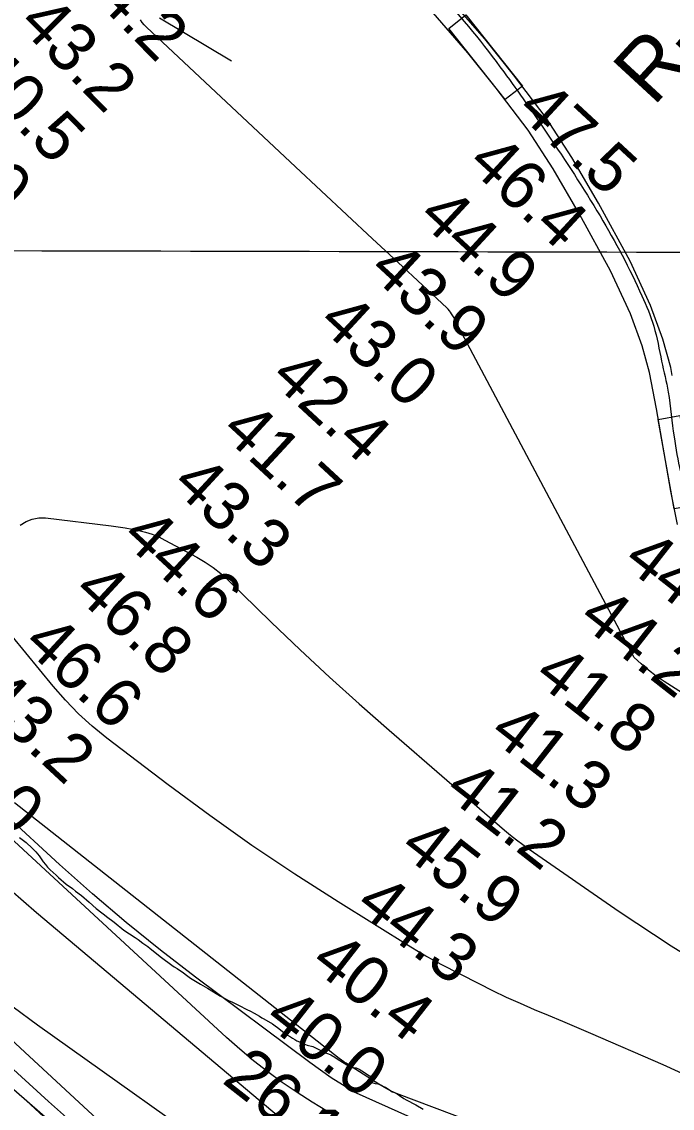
# Model space of a CAD drawing. Extents: x 3187622 to 3225504, y 800805 to 826213.
# Drawn here: x 3201041 to 3201935, y 817171 to 818665 of the extents above; entities that cross this region are included whole.
import ezdxf

# ---------------------------------------------------------------- set-up
doc = ezdxf.new("R2010")
doc.units = 0
for name, color, linetype in [('V-GRID-MAJR', 7, 'Continuous'), ('V-RIVR-EDGE', 7, 'Continuous'), ('V-RIVR-RANG', 7, 'Continuous'), ('V-RIVR-RANG-IDEN', 7, 'Continuous'), ('V-ROAD-CNTR', 7, 'Continuous'), ('V-SITE-VEGE', 7, 'Continuous'), ('V-TOPO-DPTH', 7, 'Continuous'), ('V-TOPO-MAJR', 7, 'Continuous'), ('V-TOPO-MINR', 7, 'Continuous'), ('V-TOPO-WATR', 7, 'Continuous')]:
    doc.layers.add(name, color=color, linetype=linetype)

msp = doc.modelspace()

# ---------------------------------------------------------------- linework, layer by layer
at = {"layer": 'V-GRID-MAJR'}
msp.add_spline([(3191823.839, 818371.837), (3197059.682, 818359.272), (3202295.526, 818347.468), (3207531.372, 818336.426), (3212767.22, 818326.145), (3218003.0700000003, 818316.626), (3223238.92, 818307.868), (3223238.921, 818307.868)], degree=3, dxfattribs=at)
at = {"layer": 'V-RIVR-EDGE'}
msp.add_lwpolyline([(3201136.1406451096, 817098.8818968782), (3201047.2350998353, 817181.2561007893), (3200994.754246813, 817227.8965436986)], dxfattribs=at)
at = {"layer": 'V-ROAD-CNTR'}
for points in [[(3201935.461570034, 818178.7369305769), (3201933.461920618, 818189.3653369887), (3201922.573450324, 818228.3969656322), (3201905.605787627, 818274.9007402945), (3201877.5326565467, 818335.8999269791), (3201834.216508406, 818415.3624383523), (3201797.2907217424, 818478.3515299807), (3201761.901233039, 818533.0936946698), (3201717.024386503, 818592.0773767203), (3201677.586710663, 818641.6715770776), (3201628.606678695, 818697.8135974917)], [(3201942.7374564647, 817973.6426642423), (3201933.6286105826, 818019.5790433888), (3201913.571811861, 818132.8323130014), (3201904.218079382, 818182.5486630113), (3201893.990549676, 818219.2110343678), (3201877.8422123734, 818263.4692597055), (3201850.7053434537, 818322.4340730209), (3201808.099491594, 818400.5935616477), (3201771.7412782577, 818462.6144700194), (3201737.330766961, 818515.8423053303), (3201693.3436134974, 818573.6566232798), (3201654.531289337, 818622.4644229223), (3201606.6453213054, 818677.3524025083)]]:
    msp.add_lwpolyline(points, dxfattribs=at)
for points in [[(3201705.8309982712, 818557.9533180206), (3201628.030361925, 818655.7902281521), (3201651.511220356, 818674.4623808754), (3201729.311856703, 818576.6254707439)], [(3201937.9826044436, 817994.9936622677), (3201916.184684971, 818118.0783920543), (3201945.72502012, 818123.3098927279), (3201967.5229395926, 818000.2251629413)]]:
    msp.add_lwpolyline(points, close=True, dxfattribs=at)
msp.add_spline([(3201024.1469147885, 823274.715423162), (3201018.0129270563, 823194.189584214), (3201004.718953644, 822963.7310451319), (3200987.4149882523, 822858.6972551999), (3200966.948029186, 822788.416395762), (3200937.8420873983, 822670.750631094), (3200879.4052042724, 822446.800078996), (3200861.238240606, 822331.312309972), (3200852.3482583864, 822205.904560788), (3200845.9832711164, 822103.0497664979), (3200850.494262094, 822002.651967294), (3200859.8182434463, 821900.4111717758), (3200873.148216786, 821709.08955442), (3200906.150150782, 821470.9180307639), (3200956.550049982, 821171.314629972), (3200981.83099942, 821020.504931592), (3201004.428954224, 820882.865206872), (3201024.90091328, 820767.6074373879), (3201030.704901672, 820687.434597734), (3201025.0879129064, 820574.7828230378), (3201019.728923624, 820485.638001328), (3201009.904943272, 820413.658145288), (3200981.8429993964, 820299.159374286), (3200938.6350858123, 820153.0996664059), (3200919.6651237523, 820054.1388643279), (3200905.8851513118, 819899.779173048), (3200911.078140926, 819808.036356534), (3200923.595115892, 819715.0165425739), (3200943.704075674, 819632.5057075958), (3200989.973983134, 819544.474883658), (3201077.634807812, 819388.707195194), (3201164.584633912, 819241.2794900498), (3201215.4495321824, 819169.23463414), (3201320.5073220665, 819031.1739102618), (3201438.252086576, 818874.583223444), (3201472.894017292, 818830.2363121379), (3201517.7899275, 818788.499395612), (3201613.6647357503, 818704.054564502), (3201703.731555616, 818596.021780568), (3201763.792435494, 818510.519951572), (3201836.136290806, 818397.89617682), (3201893.7711755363, 818288.104396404), (3201909.952143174, 818246.3284799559), (3201920.8531213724, 818198.082576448), (3201929.8091034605, 818155.84666092), (3201937.905087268, 818094.070784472), (3201957.718047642, 817998.595975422), (3201977.8520073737, 817926.3501199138), (3202055.382852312, 817776.5004196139), (3202147.001669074, 817623.97272467), (3202184.387594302, 817575.26282209), (3202228.252506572, 817509.5509535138), (3202265.871431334, 817464.9970426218), (3202335.4492921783, 817389.266194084), (3202595.371772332, 817156.054660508), (3202698.6155658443, 817066.2408401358), (3202845.2082726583, 816933.75410511), (3202967.1920286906, 816832.346307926), (3203084.1367948, 816744.1614842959), (3203205.803551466, 816662.3206479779), (3203334.4592941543, 816585.86980088), (3203420.0661229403, 816528.708915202), (3203529.074904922, 816448.4050758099), (3203624.28071451, 816386.379199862), (3203720.2955224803, 816332.45030772), (3203800.7433615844, 816304.608363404), (3203929.0741049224, 816241.273490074), (3204015.146932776, 816192.42558777), (3204112.488738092, 816105.381761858), (3204200.50956205, 816023.2659260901)], degree=3, dxfattribs=at)
at = {"layer": 'V-SITE-VEGE'}
for points in [[(3201037.809, 817543.368), (3201046.934, 817536.366), (3201055.403, 817528.7270000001), (3201060.1750000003, 817523.431), (3201064.617, 817517.821), (3201070.47, 817509.582), (3201073.325, 817505.953), (3201076.348, 817502.482), (3201080.174, 817498.6680000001), (3201087.997, 817491.367), (3201091.186, 817488.2170000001), (3201101.739, 817479.237), (3201110.879, 817472.888), (3201114.879, 817469.558), (3201123.2060000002, 817463.221), (3201133.764, 817454.405), (3201143.184, 817445.77), (3201150.866, 817439.61), (3201154.551, 817436.7760000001), (3201157.596, 817434.605), (3201167.842, 817426.603), (3201181.1210000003, 817415.786), (3201196.8540000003, 817405.732), (3201200.86, 817402.728), (3201207.432, 817398.05), (3201210.322, 817396.207), (3201214.168, 817393.37), (3201217.686, 817390.376), (3201232.887, 817378.055), (3201247.477, 817367.699), (3201250.686, 817365.524), (3201254.54, 817363.175)], [(3201254.54, 817363.175), (3201263.199, 817357.156), (3201267.523, 817353.821), (3201273.134, 817349.813), (3201286.622, 817341.427), (3201296.27, 817336.041), (3201310.563, 817327.15), (3201313.4590000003, 817325.631), (3201316.83, 817323.454), (3201320.846, 817321.101), (3201325.196, 817319.067), (3201329.71, 817317.191), (3201332.444, 817315.677), (3201343.552, 817310.263), (3201346.93, 817308.409), (3201350.473, 817306.715), (3201355.468, 817304.506), (3201360.455, 817301.808), (3201368.006, 817297.274), (3201371.053, 817295.265), (3201373.951, 817293.747), (3201385.682, 817286.858), (3201389.37, 817284.349), (3201392.575, 817282.012), (3201398.973, 817276.688), (3201406.186, 817271.51), (3201410.362, 817268.991), (3201413.42, 817267.308), (3201416.308, 817265.465), (3201419.363, 817263.779), (3201422.9080000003, 817262.2490000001), (3201425.647, 817260.895), (3201428.87, 817259.534), (3201433.3880000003, 817257.821), (3201441.308, 817255.552), (3201453.86, 817249.138), (3201458.372, 817247.1), (3201462.572, 817245.882), (3201465.798, 817244.518), (3201471.258, 817241.1630000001), (3201475.907, 817237.823), (3201490.042, 817229.26), (3201493.251, 817227.085), (3201497.14, 817226.524), (3201500.548, 817226.295), (3201504.904, 817224.586), (3201508.6010000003, 817222.4010000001), (3201519.193, 817215.536), (3201521.096, 817213.058), (3201520.539, 817209.495), (3201522.1010000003, 817206.214), (3201527.109, 817204.655), (3201530.355, 817204.43), (3201535.677, 817202.378), (3201538.411, 817200.86), (3201541.313, 817199.666), (3201546.769, 817195.986), (3201550.4620000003, 817193.639), (3201553.5300000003, 817192.607), (3201557.2290000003, 817190.584), (3201560.434, 817188.247), (3201566.373, 817184.394), (3201569.424, 817182.547), (3201582.613, 817175.4670000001), (3201592.739, 817169.583)]]:
    msp.add_lwpolyline(points, dxfattribs=at)
at = {"layer": 'V-TOPO-DPTH'}
for points in [[(3201349.9629572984, 817080.6381240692), (3201062.6416491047, 817285.1742495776), (3201029.1550473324, 817309.8110769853), (3200996.2071972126, 817335.1268226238), (3200964.067474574, 817361.4609456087), (3200932.4665035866, 817388.4739868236), (3200881.8476434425, 817433.1336477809), (3200876.035336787, 817438.4040445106), (3200870.32186604, 817443.7767223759), (3200864.7566491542, 817449.3028219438), (3200859.290268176, 817454.9312026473), (3200550.1939602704, 817974.9718875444), (3200377.9527381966, 818668.8148178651)], [(3201024.6007589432, 817228.5045793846), (3201077.665435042, 817180.1548996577), (3201131.415343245, 817132.5681499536)], [(3201024.6007589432, 817228.5045793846), (3201077.665435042, 817180.1548996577), (3201131.415343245, 817132.5681499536)]]:
    msp.add_lwpolyline(points, dxfattribs=at)
at = {"layer": 'V-TOPO-MAJR'}
msp.add_lwpolyline([(3202282.3889218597, 816841.8358624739), (3201497.2710883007, 817193.5666522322), (3201481.7802717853, 817203.0456578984), (3201466.509001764, 817212.8544713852), (3201451.567051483, 817223.157996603), (3201436.844647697, 817233.7913296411), (3201279.606086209, 817351.3238666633), (3201231.561461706, 817388.3899122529), (3201184.3029286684, 817426.4033321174), (3201138.2235328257, 817465.8378133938), (3201092.9302284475, 817506.2196689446), (3201017.309746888, 817575.7357708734)], dxfattribs=at)
at = {"layer": 'V-TOPO-MINR'}
for points in [[(3201395.0167852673, 817158.4609795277), (3201061.252619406, 817439.3937593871), (3201043.123074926, 817454.9788201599), (3201025.2157577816, 817470.8100407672), (3201007.641781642, 817487.0105011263), (3200990.290032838, 817503.4571213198), (3200973.2603789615, 817520.2395730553), (3200956.437577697, 817537.2232406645), (3200939.9250553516, 817554.5087320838), (3200923.6193856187, 817571.9954393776), (3200921.1083736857, 817574.7376950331), (3200903.8909131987, 817593.9083129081), (3200886.924514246, 817613.2944206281), (3200870.334707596, 817633.0037631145), (3200853.9959624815, 817652.9285954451), (3200571.5468947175, 818004.2188340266), (3200564.9232412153, 818012.7131134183), (3200558.4727459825, 818021.3329906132), (3200552.28198815, 818030.1412645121), (3200546.264388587, 818039.075136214), (3200407.1894124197, 818704.4374990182)], [(3201349.9629572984, 817080.6381240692), (3201062.6416491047, 817285.1742495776), (3201029.1550473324, 817309.8110769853), (3200996.2071972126, 817335.1268226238), (3200964.067474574, 817361.4609456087), (3200932.4665035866, 817388.4739868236), (3200881.8476434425, 817433.1336477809), (3200876.035336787, 817438.4040445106), (3200870.32186604, 817443.7767223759), (3200864.7566491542, 817449.3028219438), (3200859.290268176, 817454.9312026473), (3200550.1939602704, 817974.9718875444), (3200377.9527381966, 818668.8148178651)], [(3202094.3336253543, 817649.3835346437), (3201924.438539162, 817757.6865859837), (3201913.486547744, 817765.1954839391), (3201902.90532107, 817773.1639051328), (3201892.8802415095, 817781.8216111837), (3201883.2259266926, 817790.9388404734), (3201638.1546788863, 818251.5316376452), (3201637.5224933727, 818253.1538663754), (3201636.120060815, 818256.3323212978), (3201635.319978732, 818257.8731612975), (3201634.470463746, 818259.3898075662), (3201632.026202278, 818263.5198946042), (3201630.6357945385, 818265.6532561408), (3201629.131904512, 818267.6952431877), (3201627.4577910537, 818269.6001684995), (3201625.6701953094, 818271.4137193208), (3201558.702730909, 818333.7236645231), (3201523.360632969, 818366.639413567), (3201488.0396218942, 818399.577753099), (3201452.7502411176, 818432.5499783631), (3201417.481947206, 818465.5447941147), (3201212.532893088, 818657.4668646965), (3201209.4317356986, 818660.6820877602), (3201206.569498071, 818664.0787643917), (3201204.065640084, 818667.7476213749)], [(3201230.0956384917, 818670.1817454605), (3201329.1985597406, 818611.4196630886)], [(3201038.90231005, 817972.6436745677), (3201046.8462430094, 817977.5931281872), (3201055.194653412, 817981.137372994), (3201064.149779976, 817982.5738045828), (3201073.509383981, 817982.605027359), (3201163.915506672, 817971.6730410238), (3201173.4751859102, 817970.3914499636), (3201183.0078266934, 817968.9458855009), (3201192.499909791, 817967.2543609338), (3201201.964954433, 817965.3988629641), (3201211.26556145, 817963.0257634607), (3201220.3772827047, 817960.1357433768), (3201229.20567532, 817956.470342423), (3201237.8451821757, 817952.288020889), (3201281.7974318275, 817928.6094349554), (3201293.1903400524, 817921.8436669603), (3201304.1500539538, 817914.4872236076), (3201314.459976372, 817906.2447672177), (3201324.3367044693, 817897.4116354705), (3201384.0726317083, 817839.323234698), (3201423.8122753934, 817801.3501633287), (3201463.985069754, 817763.8493168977), (3201504.807590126, 817727.0568078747), (3201546.0632611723, 817690.7365237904), (3201704.790351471, 817553.4433032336), (3201712.9621503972, 817546.6003543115), (3201721.2731278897, 817539.9367950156), (3201729.792873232, 817533.5423201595), (3201738.4517971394, 817527.32723493), (3201862.281488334, 817441.4132080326), (3201933.976424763, 817394.1162641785), (3202007.019905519, 817349.1280079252)], [(3201118.7628371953, 817713.4129749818), (3201100.8923680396, 817731.8718136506), (3201083.8482593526, 817751.1883053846), (3201008.357275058, 817843.0011688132)], [(3201991.300607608, 817199.1944865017), (3201922.9323019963, 817230.4108245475), (3201823.4002395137, 817273.5225064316), (3201804.1085964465, 817281.8323531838), (3201784.794833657, 817290.0901750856), (3201765.4478912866, 817298.2699597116), (3201746.0788291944, 817306.3977194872), (3201726.799859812, 817314.7157981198), (3201707.662944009, 817323.3392523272), (3201688.7391085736, 817332.420769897), (3201669.9573267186, 817341.8076630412), (3201617.731335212, 817368.7000111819), (3201607.17127565, 817374.2997944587), (3201596.705967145, 817380.0667226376), (3201586.382785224, 817386.0843681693), (3201576.1543543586, 817392.2691586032), (3201475.9100066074, 817454.5470737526), (3201416.2054641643, 817492.8304987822), (3201357.266017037, 817532.2240302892), (3201299.474212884, 817573.2827215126), (3201242.4475040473, 817615.4515192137), (3201157.8092173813, 817679.9259099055), (3201137.8728470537, 817696.240615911), (3201118.7628371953, 817713.4129749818)], [(3202427.8278175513, 816862.6643597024), (3201556.2370416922, 817191.3470481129), (3201547.8663254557, 817195.0131653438), (3201539.776876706, 817199.264062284), (3201531.8749396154, 817203.9048123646), (3201490.054804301, 817230.5101203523), (3201486.842701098, 817232.6220419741), (3201483.6750811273, 817234.7967170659), (3201480.574186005, 817237.0655223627), (3201477.5177741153, 817239.3970811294), (3201031.08176724, 817590.6886283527)], [(3201461.226261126, 817166.4337687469), (3201440.0823533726, 817179.0476108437), (3201419.408316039, 817192.4176530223), (3201399.0475256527, 817206.2918285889), (3201379.224000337, 817220.9175588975), (3201359.8012338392, 817236.037974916), (3201340.979605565, 817251.9004194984), (3201322.5587361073, 817268.2575497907), (3201018.3586623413, 817549.1243726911)], [(3201256.6442505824, 817052.1544862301), (3200882.9935799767, 817397.9320824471)], [(3201255.600460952, 816999.3252388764), (3200861.2231734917, 817342.8266870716)]]:
    msp.add_lwpolyline(points, dxfattribs=at)
at = {"layer": 'V-TOPO-WATR'}
msp.add_lwpolyline([(3201131.415343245, 817132.5681499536), (3201077.665435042, 817180.1548996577), (3201024.6007589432, 817228.5045793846)], dxfattribs=at)

# ---------------------------------------------------------------- texts
at = {"layer": 'V-RIVR-RANG'}
for s, height, rotation, p in [('44.2', 67, 314.65832571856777, (3201105.0869703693, 818730.8467674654)), ('43.2', 67, 314.65832571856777, (3201034.128970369, 818660.3837674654)), ('40.5', 67, 314.65832571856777, (3200963.1709703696, 818589.9217674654)), ('47.5', 67.00000000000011, 317.2083257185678, (3201719.3262571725, 818540.8743035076)), ('41.0', 67, 314.65832571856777, (3200890.173518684, 818521.5226892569)), ('46.4', 67.00000000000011, 317.2083257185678, (3201651.578257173, 818467.3203035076)), ('44.9', 67.00000000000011, 317.2083257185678, (3201583.6356882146, 818393.9454980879)), ('43.9', 67.00000000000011, 317.2083257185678, (3201515.8876882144, 818320.392498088)), ('43.0', 67.00000000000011, 317.2083257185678, (3201446.2039986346, 818248.630443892)), ('42.4', 67.00000000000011, 317.2083257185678, (3201380.5842571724, 818173.1053035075)), ('41.7', 67.00000000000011, 317.2083257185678, (3201312.8362571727, 818099.5513035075)), ('43.3', 67.00000000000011, 317.2083257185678, (3201245.0872571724, 818025.9983035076)), ('44.6', 67.00000000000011, 317.2083257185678, (3201175.9842744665, 817953.6986655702)), ('44.9', 67.00000000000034, 321.9583257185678, (3201865.4390845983, 817918.8637155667)), ('46.8', 67.00000000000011, 317.2083257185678, (3201109.5912571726, 817878.8903035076)), ('44.2', 67.00000000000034, 321.9583257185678, (3201804.2118275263, 817839.7981655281)), ('46.6', 67.00000000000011, 317.2083257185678, (3201040.4872744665, 817806.5906655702)), ('41.8', 67.00000000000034, 321.9583257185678, (3201742.7768275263, 817760.8941655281)), ('43.2', 67.00000000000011, 317.2083257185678, (3200974.0942571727, 817731.7823035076)), ('41.3', 67.00000000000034, 321.9583257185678, (3201681.340827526, 817681.9911655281)), ('39.0', 67.00000000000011, 317.2083257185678, (3200904.2169986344, 817660.200443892)), ('41.2', 67.00000000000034, 321.9583257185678, (3201619.905827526, 817603.088165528)), ('45.9', 67.00000000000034, 321.9583257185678, (3201558.2630845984, 817524.3477155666)), ('44.3', 67.00000000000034, 321.9583257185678, (3201497.0358275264, 817445.2811655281)), ('40.4', 67.00000000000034, 321.9583257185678, (3201435.6008275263, 817366.3781655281)), ('40.0', 67.00000000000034, 321.9583257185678, (3201371.880655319, 817289.2632159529)), ('26.1', 67.00000000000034, 321.9583257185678, (3201314.5995138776, 817207.1092151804))]:
    msp.add_text(s, height=height, rotation=rotation, dxfattribs=at).set_placement(p)
at = {"layer": 'V-RIVR-RANG-IDEN'}
msp.add_text('R-276.95', height=82.9999980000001, rotation=47.35268563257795, dxfattribs=at).set_placement((3201909.401, 818547.419))

doc.saveas('drawing.dxf')
